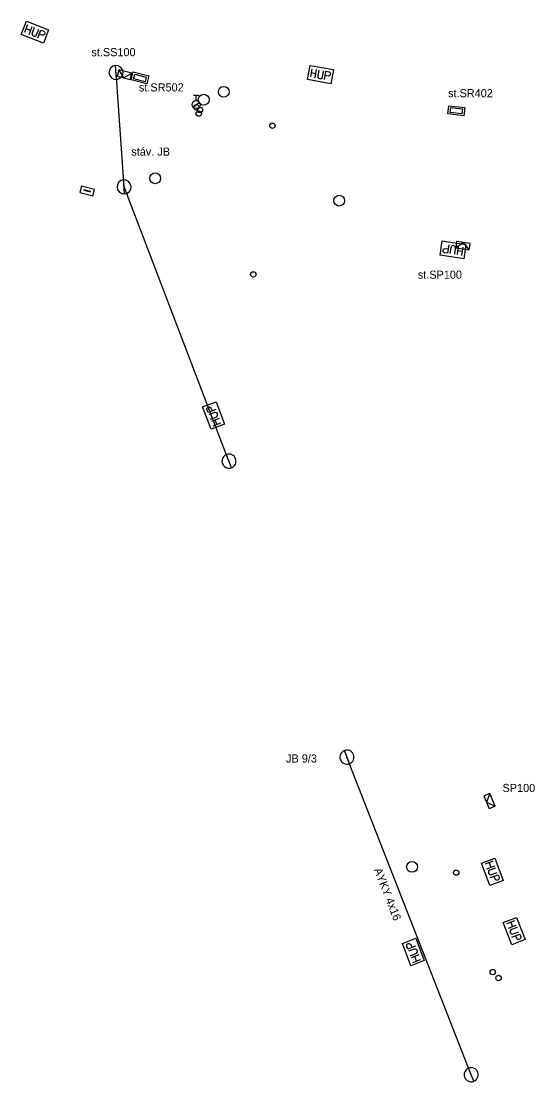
# Model space of a CAD drawing. Extents: x -762500 to -761250, y -1152983 to -1152297.
# Drawn here: x -761528.1 to -761480.7, y -1152434.4 to -1152336.7 of the extents above; entities that cross this region are included whole.
import ezdxf

# ---------------------------------------------------------------- set-up
doc = ezdxf.new("R2010")
doc.units = 0
for name, color, linetype in [('Vrstva 1', 7, 'Continuous'), ('Vrstva 2', 7, 'Continuous'), ('Vrstva 9', 7, 'Continuous')]:
    doc.layers.add(name, color=color, linetype=linetype)

msp = doc.modelspace()

# ---------------------------------------------------------------- linework, layer by layer
at = {"layer": 'Vrstva 1'}
for p, q in [((-761519.273, -1152342.018), (-761519.367, -1152340.722)), ((-761518.533, -1152352.578), (-761518.627, -1152351.282)), ((-761508.679, -1152377.827), (-761509.141, -1152376.613)), ((-761497.803, -1152405.115), (-761498.277, -1152403.905)), ((-761486.353, -1152434.405), (-761486.827, -1152433.195))]:
    msp.add_line(p, q, dxfattribs=at)
for points in [[(-761518.58, -1152351.93), (-761519.32, -1152341.37)], [(-761519.074, -1152341.132), (-761518.62, -1152341.87), (-761517.864, -1152341.446)], [(-761508.91, -1152377.22), (-761518.58, -1152351.93)], [(-761486.781, -1152357.746), (-761487.31, -1152357.06), (-761488.017, -1152357.561)], [(-761486.59, -1152433.8), (-761498.04, -1152404.51)], [(-761484.863, -1152407.864), (-761485.18, -1152408.67), (-761484.388, -1152409.02)]]:
    msp.add_lwpolyline(points, dxfattribs=at)
for points in [[(-761519.225, -1152341.713), (-761518.015, -1152342.027), (-761517.864, -1152341.446), (-761519.074, -1152341.132)], [(-761517.747, -1152341.326), (-761516.296, -1152341.703), (-761516.484, -1152342.428), (-761517.936, -1152342.052)], [(-761517.592, -1152341.521), (-761516.527, -1152341.797), (-761516.64, -1152342.233), (-761517.705, -1152341.957)], [(-761488.66, -1152344.45), (-761487.17, -1152344.62), (-761487.255, -1152345.365), (-761488.745, -1152345.195)], [(-761488.479, -1152344.622), (-761487.386, -1152344.746), (-761487.437, -1152345.193), (-761488.53, -1152345.069)], [(-761521.305, -1152352.165), (-761522.515, -1152351.855), (-761522.664, -1152352.436), (-761521.454, -1152352.746)], [(-761521.679, -1152352.366), (-761522.284, -1152352.211), (-761522.29, -1152352.235), (-761521.685, -1152352.39)], [(-761486.692, -1152357.153), (-761487.928, -1152356.967), (-761488.017, -1152357.561), (-761486.781, -1152357.746)], [(-761485.417, -1152408.092), (-761484.943, -1152409.248), (-761484.388, -1152409.02), (-761484.863, -1152407.864)]]:
    msp.add_lwpolyline(points, close=True, dxfattribs=at)
for centre, start, end in [((-761519.32, -1152341.37), 94.18241, 274.18241), ((-761519.32, -1152341.37), 274.18241, 94.18241), ((-761518.58, -1152351.93), 94.18241, 274.18241), ((-761518.58, -1152351.93), 274.18241, 94.18241), ((-761508.91, -1152377.22), 110.84328, 290.84328), ((-761508.91, -1152377.22), 290.84328, 110.84328), ((-761498.04, -1152404.51), 111.35174, 291.35174), ((-761498.04, -1152404.51), 291.35174, 111.35174), ((-761486.59, -1152433.8), 111.35174, 291.35174), ((-761486.59, -1152433.8), 291.35174, 111.35174)]:
    msp.add_arc(centre, 0.65, start, end, dxfattribs=at)
at = {"layer": 'Vrstva 9'}
for p, q in [((-761512.18, -1152343.465), (-761511.68, -1152343.465)), ((-761511.93, -1152343.965), (-761511.93, -1152343.465)), ((-761512.224, -1152344.571), (-761511.634, -1152344.108))]:
    msp.add_line(p, q, dxfattribs=at)
for points in [[(-761527.579, -1152336.652), (-761525.527, -1152337.447), (-761526.004, -1152338.677), (-761528.056, -1152337.883), (-761527.579, -1152336.652)], [(-761527.473, -1152336.988), (-761527.751, -1152337.706)], [(-761527.339, -1152337.865), (-761527.061, -1152337.147)], [(-761527.604, -1152337.326), (-761527.192, -1152337.486)], [(-761526.858, -1152337.226), (-761527.057, -1152337.741), (-761527.067, -1152337.853), (-761527.03, -1152337.945), (-761526.957, -1152338.013), (-761526.898, -1152338.036), (-761526.798, -1152338.035), (-761526.713, -1152337.99), (-761526.645, -1152337.901), (-761526.445, -1152337.386)], [(-761526.52, -1152338.183), (-761526.242, -1152337.465)], [(-761526.242, -1152337.465), (-761525.975, -1152337.568), (-761525.903, -1152337.636), (-761525.885, -1152337.681), (-761525.882, -1152337.759), (-761525.922, -1152337.862), (-761525.977, -1152337.919), (-761526.021, -1152337.94), (-761526.12, -1152337.941), (-761526.387, -1152337.838)], [(-761501.435, -1152340.724), (-761499.271, -1152341.119), (-761499.508, -1152342.417), (-761501.672, -1152342.023), (-761501.435, -1152340.724)], [(-761501.268, -1152341.034), (-761501.406, -1152341.792)], [(-761501.333, -1152341.391), (-761500.898, -1152341.47)], [(-761500.972, -1152341.871), (-761500.833, -1152341.113)], [(-761500.619, -1152341.152), (-761500.718, -1152341.696), (-761500.707, -1152341.807), (-761500.653, -1152341.891), (-761500.568, -1152341.944), (-761500.506, -1152341.956), (-761500.408, -1152341.936), (-761500.333, -1152341.876), (-761500.283, -1152341.775), (-761500.184, -1152341.232)], [(-761500.108, -1152342.028), (-761499.97, -1152341.271)], [(-761499.97, -1152341.271), (-761499.688, -1152341.322), (-761499.604, -1152341.375), (-761499.578, -1152341.417), (-761499.561, -1152341.493), (-761499.581, -1152341.601), (-761499.624, -1152341.667), (-761499.663, -1152341.696), (-761499.76, -1152341.716), (-761500.041, -1152341.664)], [(-761487.278, -1152358.549), (-761489.454, -1152358.222), (-761489.258, -1152356.917), (-761487.082, -1152357.243), (-761487.278, -1152358.549)], [(-761488.76, -1152358.048), (-761489.043, -1152358.006), (-761489.129, -1152357.955), (-761489.156, -1152357.915), (-761489.176, -1152357.839), (-761489.159, -1152357.73), (-761489.118, -1152357.663), (-761489.08, -1152357.633), (-761488.984, -1152357.61), (-761488.701, -1152357.653)], [(-761488.646, -1152357.287), (-761488.76, -1152358.048)], [(-761488.108, -1152358.146), (-761488.026, -1152357.6), (-761488.04, -1152357.489), (-761488.097, -1152357.407), (-761488.183, -1152357.356), (-761488.245, -1152357.347), (-761488.343, -1152357.37), (-761488.416, -1152357.432), (-761488.463, -1152357.535), (-761488.545, -1152358.08)], [(-761487.778, -1152357.417), (-761487.892, -1152358.178)], [(-761487.455, -1152358.244), (-761487.341, -1152357.483)], [(-761487.401, -1152357.885), (-761487.838, -1152357.819)], [(-761510.55, -1152374.269), (-761511.336, -1152372.214), (-761510.103, -1152371.743), (-761509.317, -1152373.797), (-761510.55, -1152374.269)], [(-761510.843, -1152372.732), (-761510.945, -1152372.465), (-761510.944, -1152372.366), (-761510.922, -1152372.322), (-761510.866, -1152372.268), (-761510.763, -1152372.228), (-761510.684, -1152372.231), (-761510.639, -1152372.249), (-761510.572, -1152372.322), (-761510.47, -1152372.589)], [(-761510.124, -1152372.457), (-761510.843, -1152372.732)], [(-761510.608, -1152373.349), (-761510.092, -1152373.152), (-761510.002, -1152373.084), (-761509.958, -1152372.994), (-761509.957, -1152372.894), (-761509.979, -1152372.836), (-761510.047, -1152372.762), (-761510.138, -1152372.729), (-761510.25, -1152372.739), (-761510.765, -1152372.936)], [(-761509.81, -1152373.277), (-761510.53, -1152373.552)], [(-761510.372, -1152373.965), (-761509.653, -1152373.69)], [(-761510.033, -1152373.836), (-761510.191, -1152373.423)], [(-761484.399, -1152413.818), (-761483.628, -1152415.878), (-761484.865, -1152416.34), (-761485.635, -1152414.28), (-761484.399, -1152413.818)], [(-761484.579, -1152414.12), (-761485.3, -1152414.389)], [(-761484.919, -1152414.247), (-761484.764, -1152414.661)], [(-761485.146, -1152414.803), (-761484.424, -1152414.534)], [(-761484.348, -1152414.738), (-761484.865, -1152414.931), (-761484.956, -1152414.998), (-761485, -1152415.087), (-761485.002, -1152415.188), (-761484.98, -1152415.247), (-761484.913, -1152415.321), (-761484.822, -1152415.354), (-761484.71, -1152415.345), (-761484.193, -1152415.152)], [(-761484.838, -1152415.626), (-761484.117, -1152415.356)], [(-761484.117, -1152415.356), (-761484.017, -1152415.624), (-761484.019, -1152415.723), (-761484.042, -1152415.767), (-761484.098, -1152415.821), (-761484.201, -1152415.86), (-761484.28, -1152415.856), (-761484.325, -1152415.838), (-761484.392, -1152415.764), (-761484.492, -1152415.496)], [(-761482.415, -1152419.288), (-761481.622, -1152421.341), (-761482.854, -1152421.816), (-761483.646, -1152419.764), (-761482.415, -1152419.288)], [(-761482.592, -1152419.593), (-761483.31, -1152419.87)], [(-761483.151, -1152420.282), (-761482.433, -1152420.005)], [(-761482.354, -1152420.208), (-761482.869, -1152420.407), (-761482.959, -1152420.475), (-761483.003, -1152420.565), (-761483.004, -1152420.665), (-761482.981, -1152420.724), (-761482.913, -1152420.797), (-761482.822, -1152420.83), (-761482.71, -1152420.82), (-761482.195, -1152420.621)], [(-761482.931, -1152419.723), (-761482.772, -1152420.136)], [(-761492.145, -1152423.746), (-761492.924, -1152421.689), (-761491.69, -1152421.221), (-761490.91, -1152423.279), (-761492.145, -1152423.746)], [(-761482.835, -1152421.101), (-761482.117, -1152420.824)], [(-761482.117, -1152420.824), (-761482.014, -1152421.091), (-761482.015, -1152421.19), (-761482.037, -1152421.234), (-761482.093, -1152421.289), (-761482.195, -1152421.328), (-761482.275, -1152421.326), (-761482.319, -1152421.307), (-761482.387, -1152421.235), (-761482.49, -1152420.968)], [(-761492.433, -1152422.209), (-761492.534, -1152421.941), (-761492.532, -1152421.842), (-761492.51, -1152421.799), (-761492.454, -1152421.744), (-761492.351, -1152421.705), (-761492.272, -1152421.708), (-761492.228, -1152421.727), (-761492.16, -1152421.8), (-761492.059, -1152422.067)], [(-761491.713, -1152421.936), (-761492.433, -1152422.209)], [(-761492.199, -1152422.826), (-761491.683, -1152422.63), (-761491.593, -1152422.563), (-761491.549, -1152422.474), (-761491.547, -1152422.374), (-761491.57, -1152422.315), (-761491.637, -1152422.241), (-761491.728, -1152422.208), (-761491.84, -1152422.217), (-761492.356, -1152422.413)], [(-761491.402, -1152422.757), (-761492.122, -1152423.03)], [(-761491.965, -1152423.443), (-761491.245, -1152423.17)], [(-761491.626, -1152423.315), (-761491.783, -1152422.901)]]:
    msp.add_lwpolyline(points, dxfattribs=at)
for centre, radius in [((-761509.39, -1152343.16), 0.5), ((-761511.93, -1152344.34), 0.375), ((-761511.24, -1152343.89), 0.5), ((-761511.92, -1152344.59), 0.25), ((-761511.69, -1152345.17), 0.25), ((-761511.59, -1152344.83), 0.25), ((-761504.9, -1152346.29), 0.25), ((-761515.71, -1152351.14), 0.5), ((-761498.75, -1152353.2), 0.5), ((-761506.67, -1152360), 0.25), ((-761492.04, -1152414.63), 0.5), ((-761487.97, -1152415.16), 0.25), ((-761484.6, -1152424.34), 0.25), ((-761484.07, -1152424.88), 0.25)]:
    msp.add_circle(centre, radius, dxfattribs=at)

# ---------------------------------------------------------------- texts
at = {"layer": 'Vrstva 2'}
for s, p in [('st.SS100', (-761521.59, -1152339.88)), ('st.SR502', (-761517.21, -1152343.13)), ('st.SR402', (-761488.72, -1152343.66)), ('stáv. JB', (-761517.91, -1152349.05)), ('st.SP100', (-761491.51, -1152360.4)), ('JB 9/3', (-761503.65, -1152405.01)), ('SP100', (-761483.7, -1152407.73))]:
    msp.add_text(s, height=0.75, dxfattribs=at).set_placement(p)
msp.add_text('AYKY 4x16', height=0.75, rotation=291.14446, dxfattribs=at).set_placement((-761495.56, -1152414.89))

doc.saveas('drawing.dxf')
